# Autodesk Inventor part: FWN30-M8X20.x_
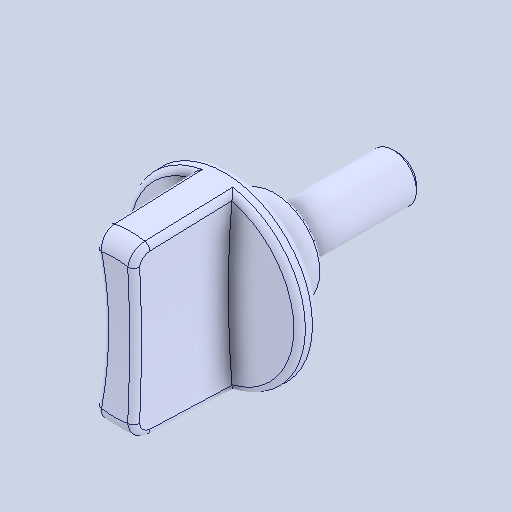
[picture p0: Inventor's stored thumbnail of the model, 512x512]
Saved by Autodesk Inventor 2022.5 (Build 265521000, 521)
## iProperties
Created: 2024-05
Part Number: FWN30-M8X20.x_
Material: 一般
Document SubType Name: Modeling
Designer: ImaoCorp
Density: 1 g/cm^3
Appearance: 既定
Author: ImaoCorp
Sending System: SOLIDWORKS 2022-2022290
MC: AMD64
MC_MODEL: Intel64 Family 6 Model 60 Stepping 3, GenuineIntel
OS: Windows_NT
FRU: Parasolid Version 33.1, build 260,  4-25-2022
FORMAT: text
GUISE: transmit
KEY: FILEFWN30-M8X20.x_t
DATE: Mon May 20 16:40:27 2024
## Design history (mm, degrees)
feature "Base1"
node "ソリッド1"
